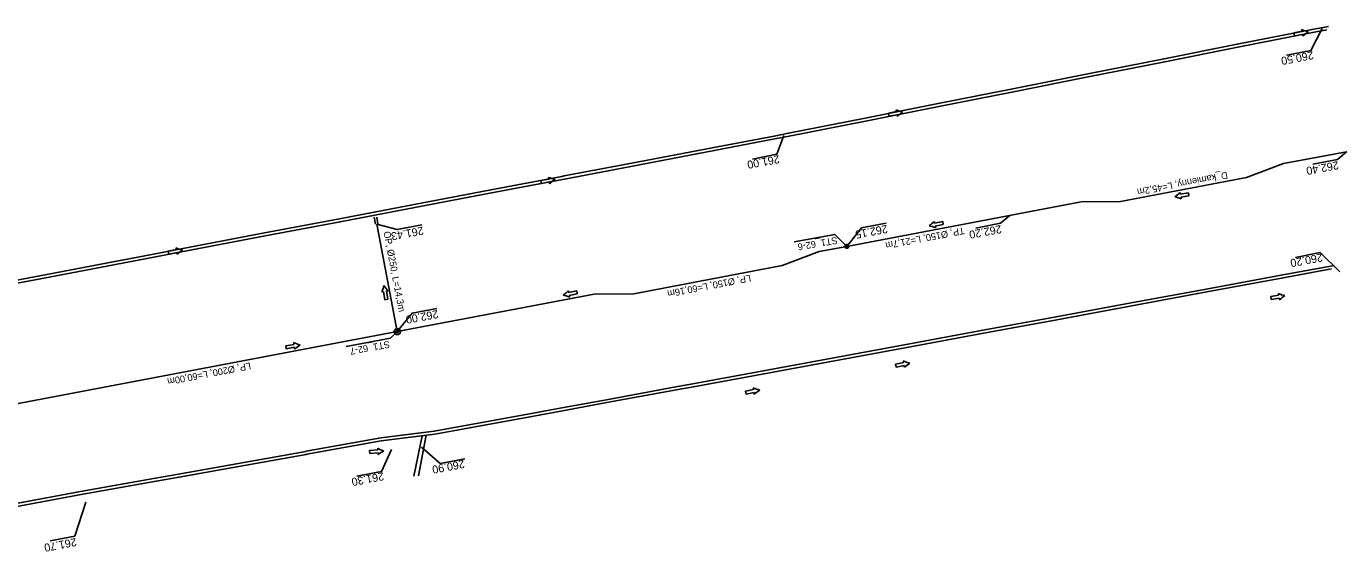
# Model space of a CAD drawing. Extents: x -1 to 65640748, y -22 to 5530284.
# Drawn here: x 6556510.5 to 6556683.1, y 5528484.2 to 5528553.1 of the extents above; entities that cross this region are included whole.
import ezdxf

# ---------------------------------------------------------------- set-up
doc = ezdxf.new("R2010")
doc.units = 0
for name, color, linetype in [('TOR_PROF-studnie i osadniki', 7, 'Continuous'), ('TOR_PS_ODW-drenaze', 7, 'Continuous'), ('TOR_PS_ODW-drenokolektory', 7, 'Continuous'), ('TOR_PS_ODW-kolektory', 7, 'Continuous'), ('TOR_PS_ODW-studnie PEHD', 7, 'Continuous'), ('TOR_PS_OPIS_O-opisy rurociagow', 7, 'Continuous'), ('TOR_PS_OPIS_O-opisy studni', 7, 'Continuous'), ('TOR_PS_OPIS_T-INFO', 7, 'Continuous'), ('TOR_PS_T-rowy otwarte umocnione', 7, 'Continuous')]:
    doc.layers.add(name, color=color, linetype=linetype)

msp = doc.modelspace()

# ---------------------------------------------------------------- linework, layer by layer
at = {"layer": 'TOR_PROF-studnie i osadniki'}
for radius in [0.25, 0.125]:
    msp.add_circle((6556618.15, 5528524.22), radius, dxfattribs=at)
at = {"layer": 'TOR_PS_ODW-drenaze'}
for points in [[(6556683.7, 5528536.64), (6556675.44, 5528535.08), (6556670.59, 5528533.24), (6556654.08, 5528530.11), (6556648.9, 5528530.05), (6556639.49, 5528528.26)], [(6556639.49, 5528528.26), (6556618.15, 5528524.22)]]:
    msp.add_lwpolyline(points, dxfattribs=at)
at = {"layer": 'TOR_PS_ODW-drenokolektory'}
for points in [[(6556618.15, 5528524.22), (6556614.52, 5528523.53), (6556609.68, 5528521.7), (6556590.22, 5528518.01), (6556585.03, 5528517.94), (6556559.2, 5528513.04)], [(6556559.2, 5528513.04), (6556500.25, 5528501.87)]]:
    msp.add_lwpolyline(points, dxfattribs=at)
at = {"layer": 'TOR_PS_ODW-kolektory'}
msp.add_line((6556559.2, 5528513.04), (6556556.53, 5528527.13), dxfattribs=at)
msp.add_lwpolyline([(6556559.2, 5528513.04), (6556556.53, 5528527.13)], dxfattribs=at)
at = {"layer": 'TOR_PS_ODW-studnie PEHD'}
for centre, radius in [((6556618.15, 5528524.22), 0.25), ((6556618.15, 5528524.22), 0.112), ((6556559.2, 5528513.04), 0.4), ((6556559.2, 5528513.04), 0.145)]:
    msp.add_circle(centre, radius, dxfattribs=at)
at = {"layer": 'TOR_PS_OPIS_O-opisy rurociagow'}
for p, q in [((6556677.88, 5528552.44), (6556676.81, 5528552.23)), ((6556677.88, 5528552.44), (6556676.81, 5528552.23)), ((6556676.81, 5528552.23), (6556676.88, 5528551.84)), ((6556676.81, 5528552.23), (6556676.88, 5528551.84)), ((6556676.88, 5528551.84), (6556677.96, 5528552.04)), ((6556677.96, 5528552.04), (6556676.88, 5528551.84)), ((6556624.69, 5528541.9), (6556623.61, 5528541.69)), ((6556624.69, 5528541.9), (6556623.61, 5528541.69)), ((6556623.61, 5528541.69), (6556623.69, 5528541.3)), ((6556623.61, 5528541.69), (6556623.69, 5528541.3)), ((6556623.69, 5528541.3), (6556624.76, 5528541.5)), ((6556624.76, 5528541.5), (6556623.69, 5528541.3)), ((6556579.1, 5528533.06), (6556578.02, 5528532.86)), ((6556579.1, 5528533.06), (6556578.02, 5528532.86)), ((6556578.02, 5528532.86), (6556578.1, 5528532.47)), ((6556578.02, 5528532.86), (6556578.1, 5528532.47)), ((6556578.1, 5528532.47), (6556579.17, 5528532.67)), ((6556579.17, 5528532.67), (6556578.1, 5528532.47)), ((6556662.98, 5528531.26), (6556661.9, 5528531.06)), ((6556661.9, 5528531.06), (6556662.98, 5528531.26)), ((6556661.98, 5528530.67), (6556663.05, 5528530.87)), ((6556661.98, 5528530.67), (6556663.05, 5528530.87)), ((6556663.05, 5528530.87), (6556662.98, 5528531.26)), ((6556663.05, 5528530.87), (6556662.98, 5528531.26)), ((6556630.74, 5528527.48), (6556629.66, 5528527.28)), ((6556629.66, 5528527.28), (6556630.74, 5528527.48)), ((6556629.74, 5528526.88), (6556630.81, 5528527.08)), ((6556629.74, 5528526.88), (6556630.81, 5528527.08)), ((6556630.81, 5528527.08), (6556630.74, 5528527.48)), ((6556630.81, 5528527.08), (6556630.74, 5528527.48)), ((6556530.23, 5528523.8), (6556529.15, 5528523.6)), ((6556530.23, 5528523.8), (6556529.15, 5528523.6)), ((6556529.15, 5528523.6), (6556529.23, 5528523.2)), ((6556529.15, 5528523.6), (6556529.23, 5528523.2)), ((6556529.23, 5528523.2), (6556530.3, 5528523.41)), ((6556530.3, 5528523.41), (6556529.23, 5528523.2)), ((6556557.37, 5528518.31), (6556557.56, 5528517.23)), ((6556557.37, 5528518.31), (6556557.56, 5528517.23)), ((6556557.95, 5528517.3), (6556557.77, 5528518.38)), ((6556557.77, 5528518.38), (6556557.95, 5528517.3)), ((6556582.73, 5528518.38), (6556581.65, 5528518.18)), ((6556581.65, 5528518.18), (6556582.73, 5528518.38)), ((6556582.8, 5528517.98), (6556582.73, 5528518.38)), ((6556582.8, 5528517.98), (6556582.73, 5528518.38)), ((6556557.56, 5528517.23), (6556557.95, 5528517.3)), ((6556557.56, 5528517.23), (6556557.95, 5528517.3)), ((6556581.73, 5528517.78), (6556582.8, 5528517.98)), ((6556581.73, 5528517.78), (6556582.8, 5528517.98)), ((6556674.84, 5528517.82), (6556673.77, 5528517.63)), ((6556674.84, 5528517.82), (6556673.77, 5528517.63)), ((6556673.77, 5528517.63), (6556673.84, 5528517.24)), ((6556673.77, 5528517.63), (6556673.84, 5528517.24)), ((6556673.84, 5528517.24), (6556674.91, 5528517.43)), ((6556674.91, 5528517.43), (6556673.84, 5528517.24)), ((6556545.65, 5528511.37), (6556544.57, 5528511.18)), ((6556545.65, 5528511.37), (6556544.57, 5528511.18)), ((6556544.57, 5528511.18), (6556544.64, 5528510.79)), ((6556544.57, 5528511.18), (6556544.64, 5528510.79)), ((6556544.64, 5528510.79), (6556545.72, 5528510.98)), ((6556545.72, 5528510.98), (6556544.64, 5528510.79)), ((6556625.63, 5528508.97), (6556624.56, 5528508.78)), ((6556625.63, 5528508.97), (6556624.56, 5528508.78)), ((6556624.56, 5528508.78), (6556624.63, 5528508.39)), ((6556624.56, 5528508.78), (6556624.63, 5528508.39)), ((6556624.63, 5528508.39), (6556625.7, 5528508.58)), ((6556625.7, 5528508.58), (6556624.63, 5528508.39)), ((6556605.94, 5528505.43), (6556604.87, 5528505.24)), ((6556605.94, 5528505.43), (6556604.87, 5528505.24)), ((6556604.87, 5528505.24), (6556604.94, 5528504.84)), ((6556604.87, 5528505.24), (6556604.94, 5528504.84)), ((6556604.94, 5528504.84), (6556606.01, 5528505.04)), ((6556606.01, 5528505.04), (6556604.94, 5528504.84)), ((6556556.66, 5528497.52), (6556555.57, 5528497.46)), ((6556556.66, 5528497.52), (6556555.57, 5528497.46)), ((6556555.57, 5528497.46), (6556555.6, 5528497.06)), ((6556555.57, 5528497.46), (6556555.6, 5528497.06)), ((6556555.6, 5528497.06), (6556556.69, 5528497.13)), ((6556556.69, 5528497.13), (6556555.6, 5528497.06))]:
    msp.add_line(p, q, dxfattribs=at)
for points in [[(6556677.83, 5528552.66), (6556677.83, 5528552.66)], [(6556677.99, 5528551.82), (6556677.99, 5528551.82)], [(6556624.63, 5528542.12), (6556624.63, 5528542.12)], [(6556624.79, 5528541.28), (6556624.79, 5528541.28)], [(6556579.04, 5528533.28), (6556579.04, 5528533.28)], [(6556579.2, 5528532.45), (6556579.2, 5528532.45)], [(6556661.87, 5528531.28), (6556661.87, 5528531.28)], [(6556662.03, 5528530.45), (6556662.03, 5528530.45)], [(6556629.63, 5528527.5), (6556629.63, 5528527.5)], [(6556629.79, 5528526.67), (6556629.79, 5528526.67)], [(6556530.17, 5528524.02), (6556530.17, 5528524.02)], [(6556530.33, 5528523.19), (6556530.33, 5528523.19)], [(6556557.99, 5528518.4), (6556557.99, 5528518.4)], [(6556581.62, 5528518.4), (6556581.62, 5528518.4)], [(6556557.15, 5528518.26), (6556557.15, 5528518.26)], [(6556581.78, 5528517.57), (6556581.78, 5528517.57)], [(6556674.79, 5528518.04), (6556674.79, 5528518.04)], [(6556674.94, 5528517.21), (6556674.94, 5528517.21)], [(6556545.6, 5528511.59), (6556545.6, 5528511.59)], [(6556545.75, 5528510.75), (6556545.75, 5528510.75)], [(6556625.58, 5528509.19), (6556625.58, 5528509.19)], [(6556625.73, 5528508.36), (6556625.73, 5528508.36)], [(6556605.89, 5528505.65), (6556605.89, 5528505.65)], [(6556606.04, 5528504.81), (6556606.04, 5528504.81)], [(6556556.64, 5528497.75), (6556556.64, 5528497.75)], [(6556556.69, 5528496.9), (6556556.69, 5528496.9)]]:
    msp.add_lwpolyline(points, dxfattribs=at)
for centre, radius, start, end in [((6556679.74, 5528557.19), 4.92, 247.1079, 257.4898), ((6556678.29, 5528552.65), 0.458, 179.2225, 207.6838), ((6556679.74, 5528557.19), 4.92, 247.1079, 257.4898), ((6556678.29, 5528552.65), 0.458, 179.2225, 207.6838), ((6556678.41, 5528552), 0.458, 173.9519, 202.4131), ((6556678.41, 5528552), 0.458, 173.9519, 202.4131), ((6556681.44, 5528548.32), 4.92, 124.1458, 134.5277), ((6556681.44, 5528548.32), 4.92, 124.1458, 134.5277), ((6556626.55, 5528546.65), 4.92, 247.1079, 257.4898), ((6556625.09, 5528542.11), 0.458, 179.2225, 207.6838), ((6556626.55, 5528546.65), 4.92, 247.1079, 257.4898), ((6556625.09, 5528542.11), 0.458, 179.2225, 207.6838), ((6556625.22, 5528541.46), 0.458, 173.9519, 202.4131), ((6556625.22, 5528541.46), 0.458, 173.9519, 202.4131), ((6556628.24, 5528537.78), 4.92, 124.1458, 134.5277), ((6556628.24, 5528537.78), 4.92, 124.1458, 134.5277), ((6556580.96, 5528537.81), 4.92, 247.1079, 257.4898), ((6556579.5, 5528533.28), 0.458, 179.2225, 207.6838), ((6556580.96, 5528537.81), 4.92, 247.1079, 257.4898), ((6556579.5, 5528533.28), 0.458, 179.2225, 207.6838), ((6556579.63, 5528532.62), 0.458, 173.9519, 202.4131), ((6556579.63, 5528532.62), 0.458, 173.9519, 202.4131), ((6556582.65, 5528528.94), 4.92, 124.1458, 134.5277), ((6556582.65, 5528528.94), 4.92, 124.1458, 134.5277), ((6556658.44, 5528534.81), 4.92, 303.7992, 314.181), ((6556658.44, 5528534.81), 4.92, 303.7992, 314.181), ((6556660.09, 5528525.93), 4.92, 66.7613, 77.1431), ((6556660.09, 5528525.93), 4.92, 66.7613, 77.1431), ((6556661.45, 5528531.11), 0.458, 353.6052, 22.0665), ((6556661.45, 5528531.11), 0.458, 353.6052, 22.0665), ((6556661.57, 5528530.46), 0.458, 358.8759, 27.3371), ((6556661.57, 5528530.46), 0.458, 358.8759, 27.3371), ((6556626.21, 5528531.03), 4.92, 303.7992, 314.181), ((6556626.21, 5528531.03), 4.92, 303.7992, 314.181), ((6556627.85, 5528522.15), 4.92, 66.7613, 77.1431), ((6556627.85, 5528522.15), 4.92, 66.7613, 77.1431), ((6556629.21, 5528527.33), 0.458, 353.6052, 22.0665), ((6556629.21, 5528527.33), 0.458, 353.6052, 22.0665), ((6556629.33, 5528526.67), 0.458, 358.8759, 27.3371), ((6556629.33, 5528526.67), 0.458, 358.8759, 27.3371), ((6556532.09, 5528528.55), 4.92, 247.1079, 257.4898), ((6556530.63, 5528524.01), 0.458, 179.2225, 207.6838), ((6556532.09, 5528528.55), 4.92, 247.1079, 257.4898), ((6556530.63, 5528524.01), 0.458, 179.2225, 207.6838), ((6556533.78, 5528519.68), 4.92, 124.1458, 134.5277), ((6556533.78, 5528519.68), 4.92, 124.1458, 134.5277), ((6556530.76, 5528523.36), 0.458, 173.9519, 202.4131), ((6556530.76, 5528523.36), 0.458, 173.9519, 202.4131), ((6556552.66, 5528520.25), 4.92, 336.1449, 346.5268), ((6556552.66, 5528520.25), 4.92, 336.1449, 346.5268), ((6556557.17, 5528518.72), 0.458, 268.2595, 296.7208), ((6556557.17, 5528518.72), 0.458, 268.2595, 296.7208), ((6556561.55, 5528521.79), 4.92, 213.1828, 223.5647), ((6556561.55, 5528521.79), 4.92, 213.1828, 223.5647), ((6556557.82, 5528518.83), 0.458, 262.9889, 291.4501), ((6556557.82, 5528518.83), 0.458, 262.9889, 291.4501), ((6556578.2, 5528521.93), 4.92, 303.7992, 314.181), ((6556578.2, 5528521.93), 4.92, 303.7992, 314.181), ((6556581.2, 5528518.23), 0.458, 353.6052, 22.0665), ((6556581.2, 5528518.23), 0.458, 353.6052, 22.0665), ((6556579.84, 5528513.05), 4.92, 66.7613, 77.1431), ((6556579.84, 5528513.05), 4.92, 66.7613, 77.1431), ((6556581.32, 5528517.57), 0.458, 358.8759, 27.3371), ((6556581.32, 5528517.57), 0.458, 358.8759, 27.3371), ((6556676.75, 5528522.55), 4.92, 246.4853, 256.8672), ((6556675.25, 5528518.03), 0.458, 178.5999, 207.0611), ((6556676.75, 5528522.55), 4.92, 246.4853, 256.8672), ((6556675.25, 5528518.03), 0.458, 178.5999, 207.0611), ((6556675.37, 5528517.38), 0.458, 173.3292, 201.7905), ((6556675.37, 5528517.38), 0.458, 173.3292, 201.7905), ((6556678.35, 5528513.66), 4.92, 123.5232, 133.905), ((6556678.35, 5528513.66), 4.92, 123.5232, 133.905), ((6556547.59, 5528516.09), 4.92, 246.1449, 256.5268), ((6556546.06, 5528511.58), 0.458, 178.2595, 206.7208), ((6556547.59, 5528516.09), 4.92, 246.1449, 256.5268), ((6556546.06, 5528511.58), 0.458, 178.2595, 206.7208), ((6556546.17, 5528510.92), 0.458, 172.9889, 201.4501), ((6556546.17, 5528510.92), 0.458, 172.9889, 201.4501), ((6556549.14, 5528507.19), 4.92, 123.1828, 133.5647), ((6556549.14, 5528507.19), 4.92, 123.1828, 133.5647), ((6556627.54, 5528513.7), 4.92, 246.4853, 256.8672), ((6556626.04, 5528509.18), 0.458, 178.5999, 207.0611), ((6556627.54, 5528513.7), 4.92, 246.4853, 256.8672), ((6556626.04, 5528509.18), 0.458, 178.5999, 207.0611), ((6556626.16, 5528508.53), 0.458, 173.3292, 201.7905), ((6556626.16, 5528508.53), 0.458, 173.3292, 201.7905), ((6556629.14, 5528504.81), 4.92, 123.5232, 133.905), ((6556629.14, 5528504.81), 4.92, 123.5232, 133.905), ((6556607.86, 5528510.16), 4.92, 246.4678, 256.8496), ((6556606.35, 5528505.64), 0.458, 178.5823, 207.0436), ((6556607.86, 5528510.16), 4.92, 246.4678, 256.8496), ((6556606.35, 5528505.64), 0.458, 178.5823, 207.0436), ((6556606.47, 5528504.98), 0.458, 173.3117, 201.7729), ((6556606.47, 5528504.98), 0.458, 173.3117, 201.7729), ((6556609.45, 5528501.27), 4.92, 123.5057, 133.8875), ((6556609.45, 5528501.27), 4.92, 123.5057, 133.8875), ((6556557.09, 5528497.68), 0.458, 171.9419, 200.4031), ((6556557.09, 5528497.68), 0.458, 171.9419, 200.4031), ((6556559.11, 5528502), 4.92, 239.8273, 250.2091), ((6556559.11, 5528502), 4.92, 239.8273, 250.2091), ((6556557.13, 5528497.02), 0.458, 166.6712, 195.1325), ((6556557.13, 5528497.02), 0.458, 166.6712, 195.1325), ((6556559.67, 5528492.99), 4.92, 116.8652, 127.247), ((6556559.67, 5528492.99), 4.92, 116.8652, 127.247)]:
    msp.add_arc(centre, radius, start, end, dxfattribs=at)
at = {"layer": 'TOR_PS_OPIS_T-INFO'}
for points in [[(6556680.53, 5528552.82), (6556679.05, 5528549.93), (6556675.82, 5528549.31)], [(6556609.88, 5528538.76), (6556609, 5528536.3), (6556605.77, 5528535.68)], [(6556683.74, 5528536.65), (6556682.54, 5528535.63), (6556679.3, 5528535.01)], [(6556556.53, 5528527.13), (6556559.19, 5528526.42), (6556562.43, 5528527.03)], [(6556618.15, 5528524.22), (6556620.08, 5528526.65), (6556623.32, 5528527.25)], [(6556639.53, 5528528.27), (6556638.32, 5528527.25), (6556635.09, 5528526.63)], [(6556618.15, 5528524.22), (6556616.58, 5528525.8), (6556611.24, 5528524.81)], [(6556682.85, 5528520.9), (6556680.26, 5528523.4), (6556677.02, 5528522.77)], [(6556559.2, 5528513.04), (6556561.13, 5528515.48), (6556564.37, 5528516.08)], [(6556559.2, 5528513.04), (6556558.29, 5528512.16), (6556552.49, 5528511.07)], [(6556562.38, 5528497.9), (6556564.81, 5528495.75), (6556568.05, 5528496.35)], [(6556558.42, 5528497.56), (6556557.11, 5528494.69), (6556553.88, 5528494.07)], [(6556518.33, 5528490.67), (6556516.88, 5528486.22), (6556513.65, 5528485.6)]]:
    msp.add_lwpolyline(points, dxfattribs=at)
at = {"layer": 'TOR_PS_T-rowy otwarte umocnione'}
for p, q in [((6556556.33, 5528527.14), (6556556.16, 5528528.04)), ((6556556.66, 5528527.17), (6556556.49, 5528528.05)), ((6556561.37, 5528494.08), (6556562.47, 5528499.37)), ((6556561.97, 5528494.13), (6556562.99, 5528499.44))]:
    msp.add_line(p, q, dxfattribs=at)
for points in [[(6556681.34, 5528553.09), (6556679.19, 5528552.69), (6556669.38, 5528550.74), (6556659.57, 5528548.8), (6556649.77, 5528546.85), (6556639.96, 5528544.9), (6556630.15, 5528542.96), (6556620.34, 5528541.01), (6556610.53, 5528539.06), (6556608.62, 5528538.7), (6556600.71, 5528537.19), (6556590.89, 5528535.33), (6556581.07, 5528533.46), (6556580.8, 5528533.41), (6556571.25, 5528531.59), (6556561.43, 5528529.72), (6556552.97, 5528528.11), (6556551.61, 5528527.85), (6556541.78, 5528525.98), (6556531.96, 5528524.11), (6556525.15, 5528522.81), (6556522.14, 5528522.24), (6556512.32, 5528520.37), (6556502.5, 5528518.5)], [(6556681.12, 5528552.64), (6556679.27, 5528552.3), (6556669.46, 5528550.35), (6556659.65, 5528548.4), (6556649.84, 5528546.46), (6556640.03, 5528544.51), (6556630.22, 5528542.56), (6556620.41, 5528540.62), (6556610.6, 5528538.67), (6556608.7, 5528538.31), (6556600.78, 5528536.8), (6556590.96, 5528534.93), (6556581.14, 5528533.06), (6556580.87, 5528533.01), (6556571.32, 5528531.19), (6556561.5, 5528529.33), (6556553.05, 5528527.72), (6556551.68, 5528527.46), (6556541.86, 5528525.59), (6556532.04, 5528523.72), (6556525.22, 5528522.42), (6556522.22, 5528521.85), (6556512.39, 5528519.98), (6556502.57, 5528518.11)], [(6556682.09, 5528521.73), (6556675.13, 5528520.45), (6556665.29, 5528518.63), (6556655.46, 5528516.81), (6556645.62, 5528515), (6556635.79, 5528513.18), (6556625.96, 5528511.36), (6556606.29, 5528507.73)], [(6556681.75, 5528521.26), (6556675.2, 5528520.05), (6556665.37, 5528518.24), (6556655.53, 5528516.42), (6556645.7, 5528514.6), (6556635.87, 5528512.79), (6556626.03, 5528510.97), (6556606.36, 5528507.34)], [(6556606.29, 5528507.73), (6556597.5, 5528506.11), (6556596.45, 5528505.92), (6556586.62, 5528504.11), (6556580.77, 5528503.04), (6556576.78, 5528502.3), (6556566.94, 5528500.5), (6556564.05, 5528499.97), (6556557.03, 5528499.1), (6556547.24, 5528497.34), (6556547.18, 5528497.33), (6556537.34, 5528495.57), (6556530.51, 5528494.35), (6556527.49, 5528493.81), (6556517.65, 5528492.05), (6556507.82, 5528490.22)], [(6556606.36, 5528507.34), (6556597.57, 5528505.72), (6556596.53, 5528505.53), (6556586.69, 5528503.72), (6556580.85, 5528502.64), (6556576.85, 5528501.91), (6556567.02, 5528500.11), (6556564.12, 5528499.58), (6556557.1, 5528498.71), (6556547.32, 5528496.95), (6556547.26, 5528496.94), (6556537.41, 5528495.17), (6556530.58, 5528493.95), (6556527.57, 5528493.41), (6556517.72, 5528491.65), (6556507.89, 5528489.82)]]:
    msp.add_lwpolyline(points, dxfattribs=at)

# ---------------------------------------------------------------- texts
at = {"layer": 'TOR_PS_OPIS_O-opisy rurociagow'}
for s, rotation, p in [('D_kamienny, L=45,2m', 190.7332, (6556668.04, 5528534.02)), ('OP, Ø250, L=14,3m', 280.821, (6556557.38, 5528526.11)), ('TP, Ø150, L=21,7m', 190.9157, (6556633.51, 5528526.74)), ('LP, Ø150, L=60,16m', 190.9157, (6556605.49, 5528520.52)), ('LP, Ø200, L=60,00m', 190.9157, (6556539.9, 5528509))]:
    msp.add_text(s, height=0.9, rotation=rotation, dxfattribs=at).set_placement(p)
at = {"layer": 'TOR_PS_OPIS_O-opisy studni'}
for s, rotation, p in [('ST1_62-6', 189.8873, (6556616.86, 5528525.47)), ('ST1_62-7', 190.4184, (6556558.12, 5528511.83))]:
    msp.add_text(s, height=0.9, rotation=rotation, dxfattribs=at).set_placement(p)
at = {"layer": 'TOR_PS_OPIS_T-INFO'}
for s, rotation, p in [('260.50', 190.7159, (6556679.28, 5528549.84)), ('261.00', 190.7159, (6556609.24, 5528536.21)), ('262.40', 190.7159, (6556682.58, 5528535.41)), ('262.15', 190.7506, (6556623.42, 5528527.05)), ('262.20', 190.7159, (6556638.36, 5528527.03)), ('261.43', 190.7506, (6556562.53, 5528526.82)), ('260.20', 190.7159, (6556680.49, 5528523.31)), ('262.00', 190.7506, (6556564.46, 5528515.88)), ('260.90', 190.7506, (6556567.92, 5528496.21)), ('261.30', 190.7159, (6556557.34, 5528494.6)), ('261.70', 190.7159, (6556517.02, 5528485.97))]:
    msp.add_text(s, height=1.05, rotation=rotation, dxfattribs=at).set_placement(p)

doc.saveas('drawing.dxf')
